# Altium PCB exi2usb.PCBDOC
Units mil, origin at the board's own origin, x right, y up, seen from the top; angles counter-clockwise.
Board outline 1185 x 2070 mil, 4 copper layers (Top Layer, Internal Plane 1, Internal Plane 2, Bottom Layer); 25 components, 72 nets, 205 pads, 65 vias.
Unrouted connection lines stored in the file: 5.
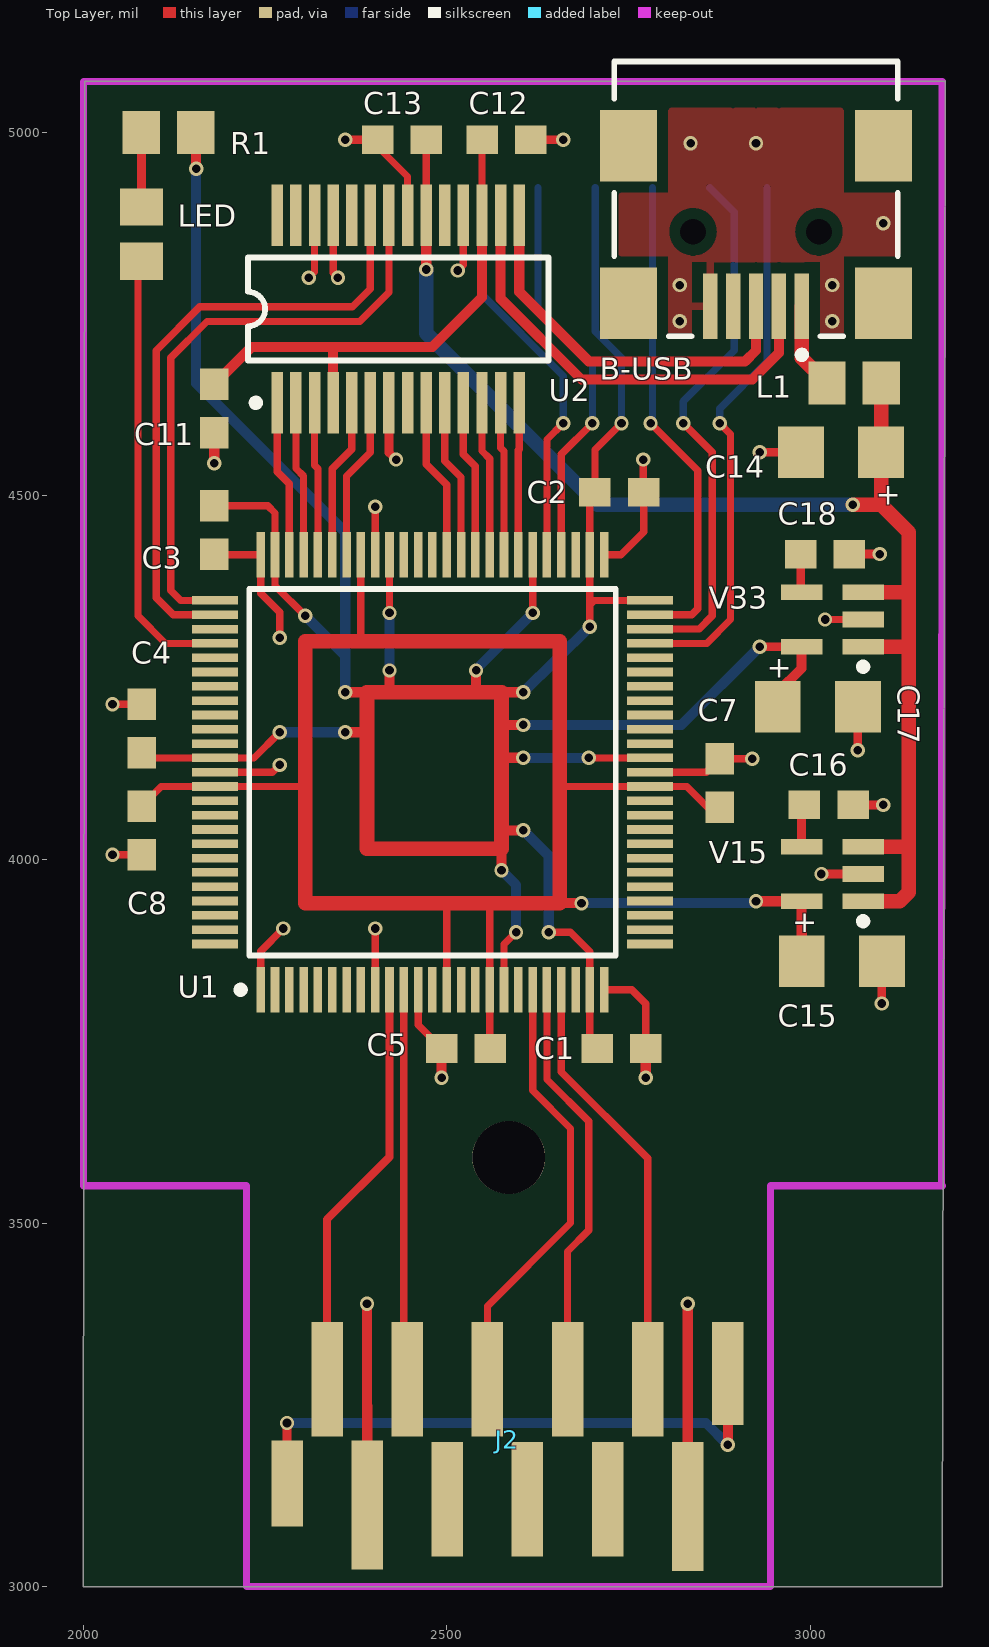
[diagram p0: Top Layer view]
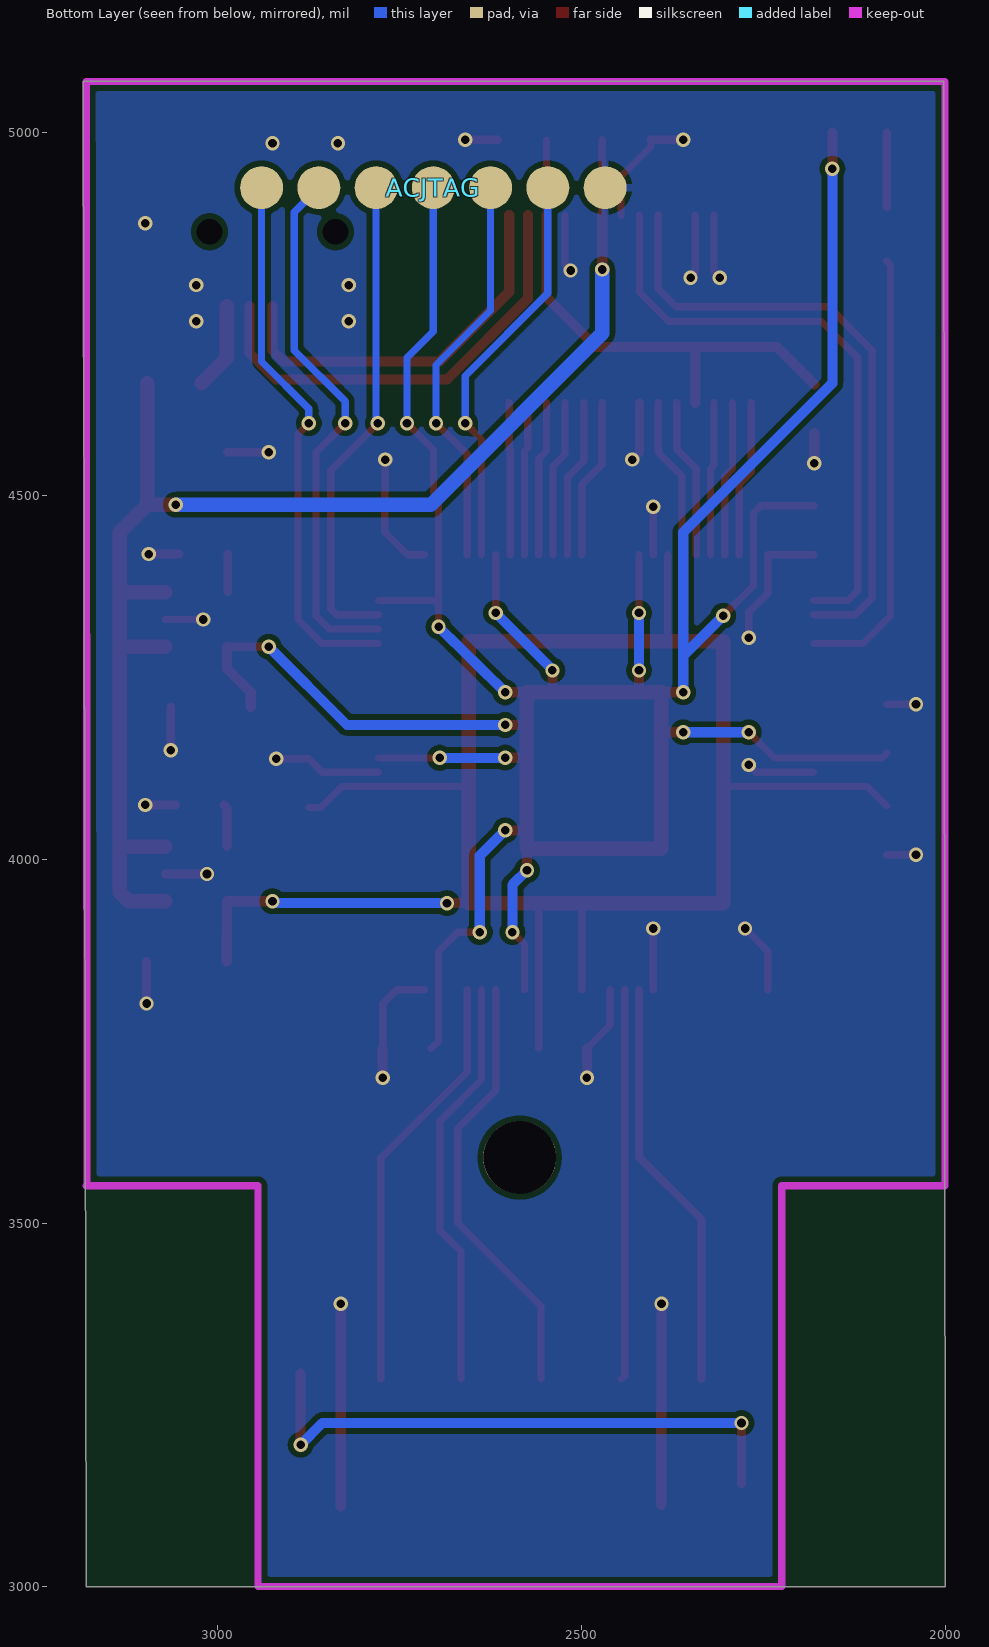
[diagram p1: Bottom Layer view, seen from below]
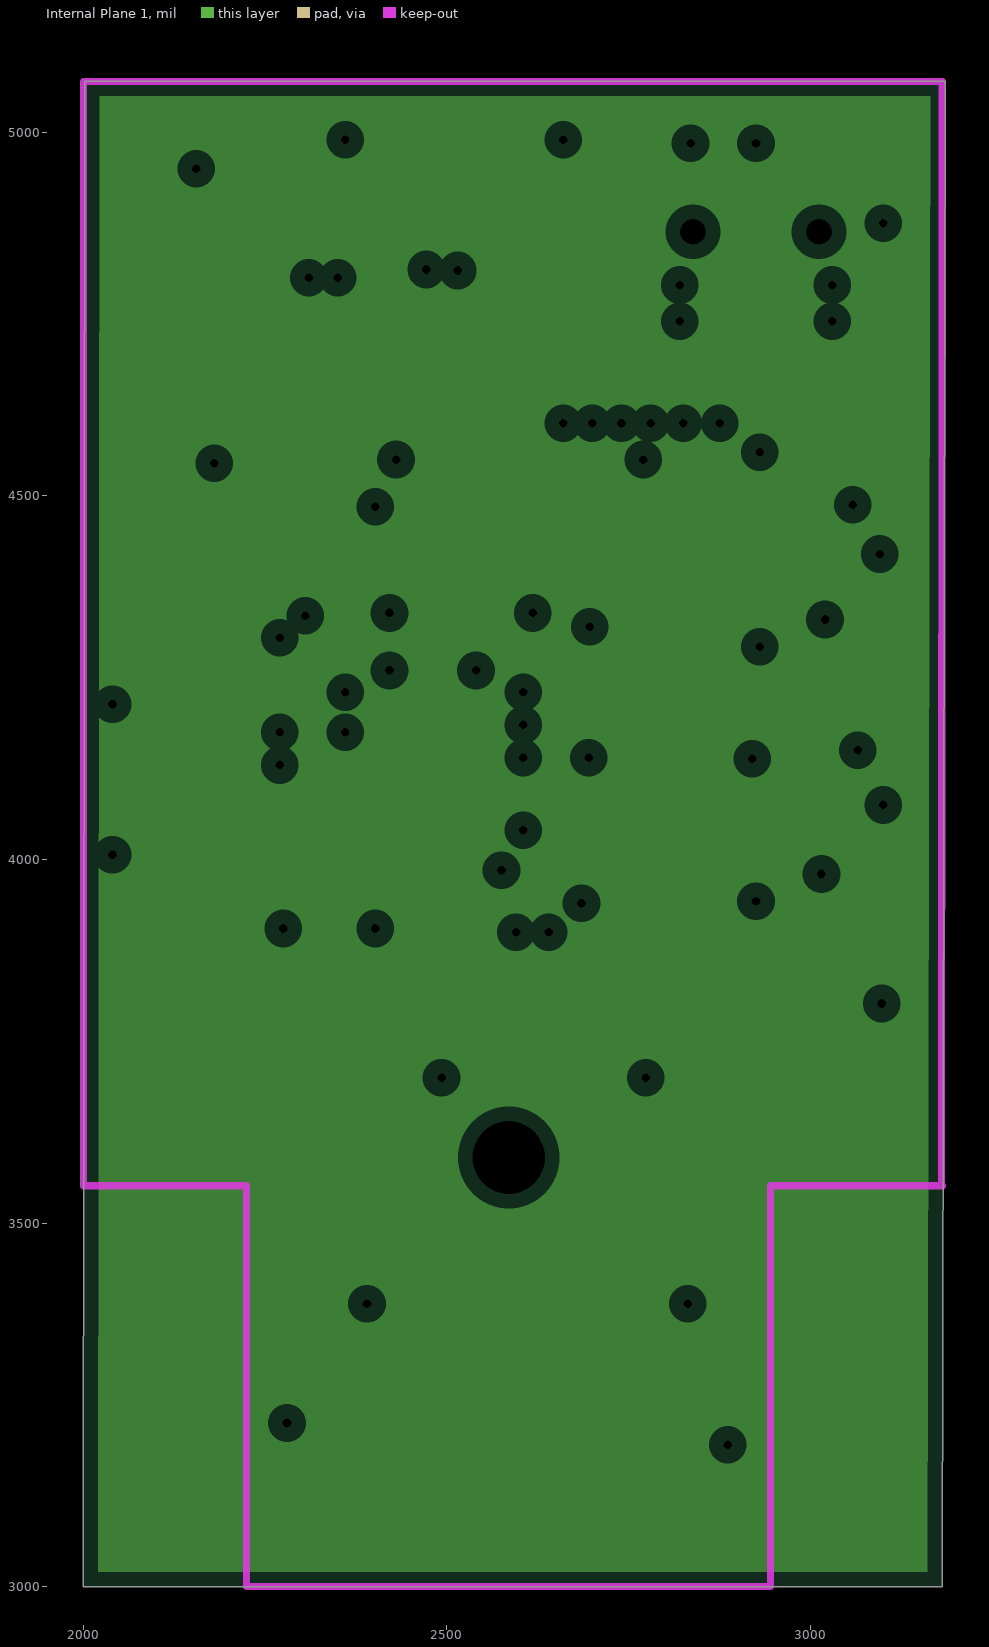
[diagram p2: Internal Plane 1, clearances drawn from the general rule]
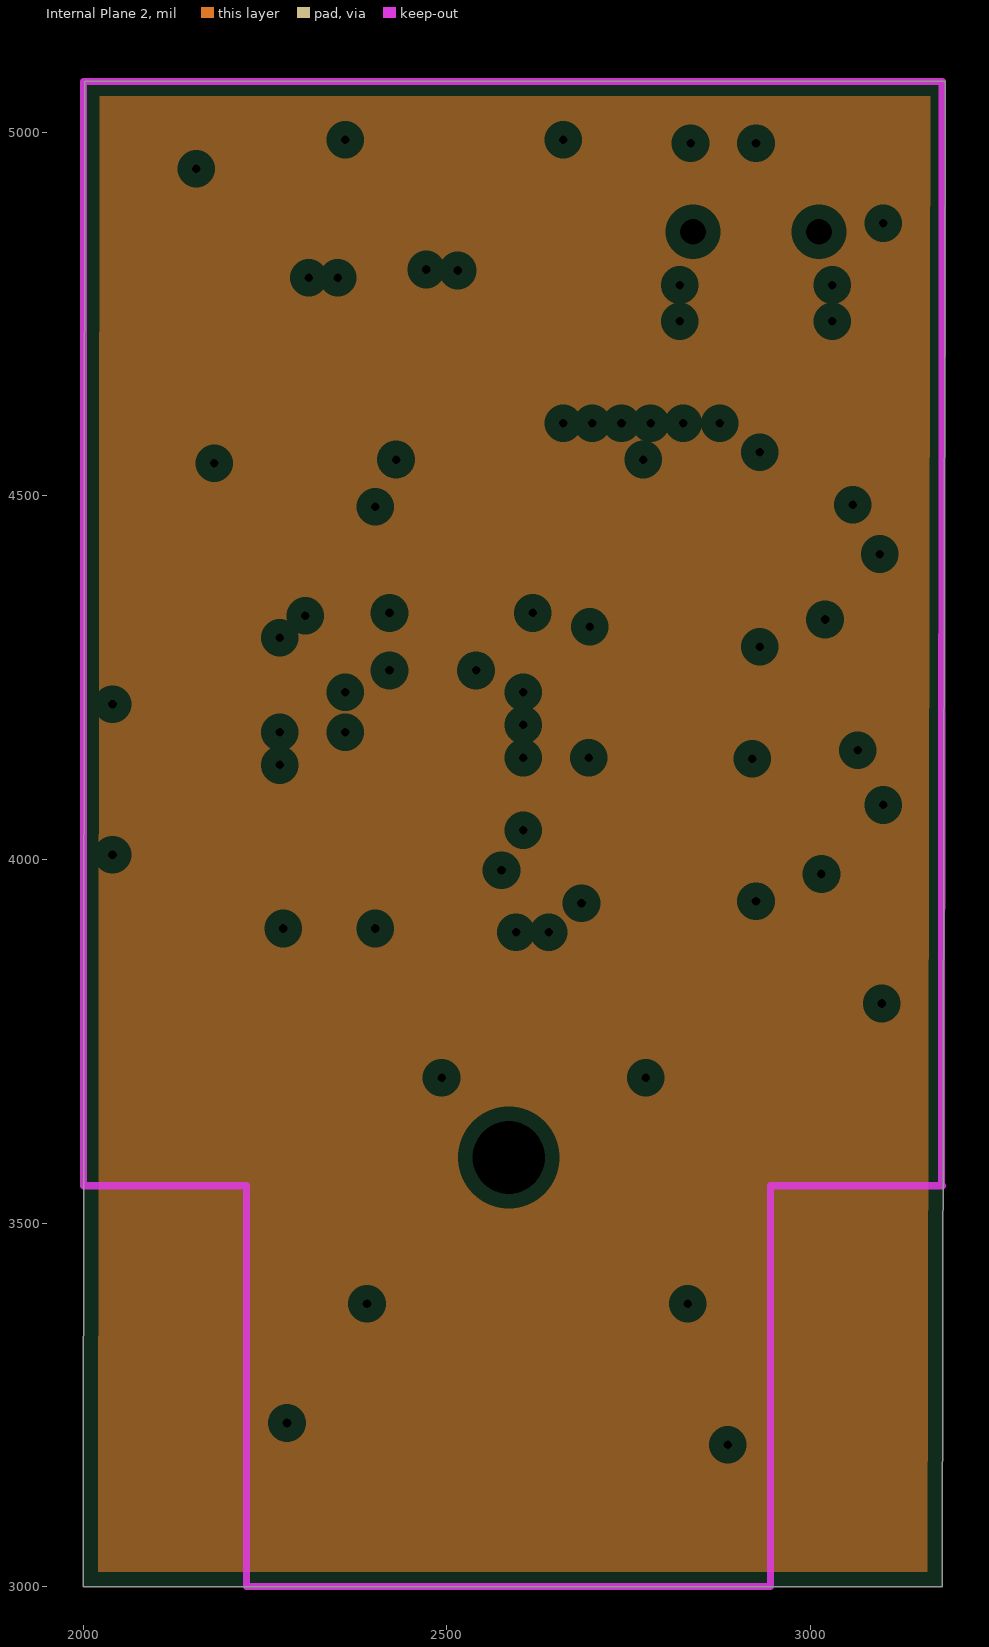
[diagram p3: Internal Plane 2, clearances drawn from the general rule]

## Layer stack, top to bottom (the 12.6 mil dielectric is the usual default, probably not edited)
Top Layer: signal copper 1.4
Dielectric: dielectric 12.6, FR-4, Dk 4.8
Internal Plane 1: plane copper 1.4
Dielectric: dielectric 12.6, FR-4, Dk 4.8
Internal Plane 2: plane copper 1.4
Dielectric: dielectric 12.6, FR-4, Dk 4.8
Bottom Layer: signal copper 1.4

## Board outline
2000,3000 3181.1,3000 3185,5070 2002,5070

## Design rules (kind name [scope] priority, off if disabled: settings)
Clearance [All] p1: gap=7
ComponentClearance [All] p1: gap=10 collisioncheckmode=0
PlaneClearance [All] p1: clearance=20
PlaneConnect [All] p1: planeconnectstyle=Relief reliefexpansion=20 reliefentries=4 reliefconductorwidth=10 reliefairgap=10
PolygonConnect [All] p1: connectstyle=Relief reliefconductorwidth=10 reliefentries=4 polygonreliefangle="90 Angle"
RoomDefinition exi2usb [InComponentClass('exi2usb')] p1: confinementstyle=ConfineIn formatcopy=TRUE outline 0,0 2000,0 2000,1000 0,1000
RoutingLayers [All] p1: top layer=Horizontal bottom layer=Vertical
RoutingVias [All] p1: holewidth=23.62 width=39.37 viastyle="Through Hole" minholewidth=28 minwidth=50 maxholewidth=28 maxwidth=50
SolderMaskExpansion [All] p1: expansion=4
TestPointUsage [All] p1: valid=0 allowmultiple=FALSE
Testpoint [All] p1: side=15 testpointundercomponent=TRUE minsize=40 maxsize=100 preferedsize=60 minholesize=0 maxholesize=40 preferedholesize=32 testpointgrid=1 style=1023 order=1234567890
Width [All] p1: maxlimit=20 minlimit=6 preferedwidth=6
14 further rules are at their usual default settings.

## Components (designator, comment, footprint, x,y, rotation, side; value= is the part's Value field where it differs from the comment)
ACJTAG "JTAG_1" ACTJTAG 2940,4924 r180 bottom
B-USB "USB-Btype" Mini-USB-SMT 2925,5070 r90 top (schematic designator J1)
C1 "CAP603" CAP0603 2740,3740 r0 top
C2 "CAP603" CAP0603 2737,4505 r0 top
C3 "CAP603" CAP0603 2180,4453 r270 top
C4 "CAP603" CAP0603 2080,4180 r90 top
C5 "CAP603" CAP0603 2526,3740 r180 top
C7 "CAP603" CAP0603 2875,4105 r90 top
C8 "CAP603" CAP0603 2080,4040 r270 top
C11 "CAP603" CAP0603 2180,4620 r270 top
C12 "0.1uF" CAP0603 2582,4990 r0 top
C13 "CAP603" CAP0603 2438,4990 r180 top
C14 "TANT1206" CAP1206 3042,4560 r180 top
C15 "TANT1206" CAP1206 3043,3860 r0 top
C16 "CAP603" CAP0603 3025,4075 r0 top
C17 "TANT1206" CAP1206 3010,4210 r0 top
C18 "CAP603" CAP0603 3020,4420 r0 top
J2 "GCMEMPADS" GCMEMPADS 2280,3120 r0 top (schematic designator U4)
L1 "Ferrite Bead" RES0805 3060,4655 r180 top (schematic designator FB1)
LED "LED" RES0805 2080,4860 r90 top (schematic designator R1)
R1 "R1K" RES0805 2117,5000 r180 top (schematic designator R2)
U1 "A3P125" ACTELVQ100 2480,4120 r90 top
U2 "FTDI245RL" SSO-G28/X.4 2433,4757 r0 top
V15 "1.5V Reg" SO-G5/P.95 3030,3980 r90 top
V33 "3.3V Reg" SO-G5/P.95 3030,4330 r90 top

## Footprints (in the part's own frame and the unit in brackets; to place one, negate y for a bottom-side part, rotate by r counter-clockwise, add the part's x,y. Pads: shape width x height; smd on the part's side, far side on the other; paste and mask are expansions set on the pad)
ACTELVQ100 [mm]
  rect 1.6x0.3 smd: 1(-7.6,6) 2(-7.6,5.5) 3(-7.6,5) 4(-7.6,4.5) 5(-7.6,4) 6(-7.6,3.5) 7(-7.6,3) 8(-7.6,2.5) 9(-7.6,2) 10(-7.6,1.5) 11(-7.6,1) 12(-7.6,0.5) 13(-7.6,0) 14(-7.6,-0.5) 15(-7.6,-1) 16(-7.6,-1.5) 17(-7.6,-2) 18(-7.6,-2.5) 19(-7.6,-3) 20(-7.6,-3.5) 21(-7.6,-4) 22(-7.6,-4.5) 23(-7.6,-5) 24(-7.6,-5.5) 25(-7.6,-6) 51(7.6,-6) 52(7.6,-5.5) 53(7.6,-5) 54(7.6,-4.5) 55(7.6,-4) 56(7.6,-3.5) 57(7.6,-3) 58(7.6,-2.5) 59(7.6,-2) 60(7.6,-1.5) 61(7.6,-1) 62(7.6,-0.5) 63(7.6,0) 64(7.6,0.5) 65(7.6,1) 66(7.6,1.5) 67(7.6,2) 68(7.6,2.5) 69(7.6,3) 70(7.6,3.5) 71(7.6,4) 72(7.6,4.5) 73(7.6,5) 74(7.6,5.5) 75(7.6,6)
  rect 0.3x1.6 smd: 26(-6,-7.6) 27(-5.5,-7.6) 28(-5,-7.6) 29(-4.5,-7.6) 30(-4,-7.6) 31(-3.5,-7.6) 32(-3,-7.6) 33(-2.5,-7.6) 34(-2,-7.6) 35(-1.5,-7.6) 36(-1,-7.6) 37(-0.5,-7.6) 38(0,-7.6) 39(0.5,-7.6) 40(1,-7.6) 41(1.5,-7.6) 42(2,-7.6) 43(2.5,-7.6) 44(3,-7.6) 45(3.5,-7.6) 46(4,-7.6) 47(4.5,-7.6) 48(5,-7.6) 49(5.5,-7.6) 50(6,-7.6) 76(6,7.6) 77(5.5,7.6) 78(5,7.6) 79(4.5,7.6) 80(4,7.6) 81(3.5,7.6) 82(3,7.6) 83(2.5,7.6) 84(2,7.6) 85(1.5,7.6) 86(1,7.6) 87(0.5,7.6) 88(0,7.6) 89(-0.5,7.6) 90(-1,7.6) 91(-1.5,7.6) 92(-2,7.6) 93(-2.5,7.6) 94(-3,7.6) 95(-3.5,7.6) 96(-4,7.6) 97(-4.5,7.6) 98(-5,7.6) 99(-5.5,7.6) 100(-6,7.6)
  silkscreen extent -7.72,-6.4 6.4,6.82
ACTJTAG [mm]
  round 1.5 smd: 1(0,0) 2(2,0) 3(4,0) 4(6,0) 5(8,0) 6(10,0) 7(12,0)
CAP0603 [mm]
  rect 1.1x1 smd: 1(-0.85,0) 2(0.85,0)
CAP1206 [mm]
  rect 1.6x1.8 smd: 1(-1.4,0) 2(1.4,0)
GCMEMPADS [mm]
  rect 1.1x3.6 smd: 1(15.4,4.4)
  rect 1.1x4.5 smd: 2(14,-0.25) 10(2.8,-0.2)
  rect 1.1x4 smd: 3(12.6,4.2) 4(11.2,0) 5(9.8,4.2) 6(8.4,0) 7(7,4.2) 8(5.6,0) 9(4.2,4.2) 11(1.4,4.2)
  rect 1.1x3 smd: 12(0,0.55)
Mini-USB-SMT [mm]
  rect 2.3x0.5 smd: 1(-7.85,-1.6) 2(-7.85,-0.8) 3(-7.85,0) 4(-7.85,0.8) 5(-7.85,1.6)
  rect 2.5x2 smd: 6(-7.75,4.45) 7(-2.25,4.45) 8(-7.75,-4.45) 9(-2.25,-4.45)
  round 0.6 hole 0.9 unplated: MH1(-5.25,2.2) MH2(-5.25,-2.2)
  silkscreen extent -9.67,-4.95 0.7,4.95
RES0805 [mm]
  rect 1.3x1.5 smd: 1(-0.95,0) 2(0.95,0)
SO-G5/P.95 [mm]
  rect 0.55x1.45 smd: 1(-0.95,-1.075) 2(0,-1.075) 3(0.95,-1.075) 4(0.95,1.075) 5(-0.95,1.075)
  silkscreen extent -1.77,-1.2 -1.52,-0.95
SSO-G28/X.4 [mm]
  rect 0.4x2.15 smd: 1(-4.225,-3.275) 2(-3.575,-3.275) 3(-2.925,-3.275) 4(-2.275,-3.275) 5(-1.625,-3.275) 6(-0.975,-3.275) 7(-0.325,-3.275) 8(0.325,-3.275) 9(0.975,-3.275) 10(1.625,-3.275) 11(2.275,-3.275) 12(2.925,-3.275) 13(3.575,-3.275) 14(4.225,-3.275) 15(4.225,3.275) 16(3.575,3.275) 17(2.925,3.275) 18(2.275,3.275) 19(1.625,3.275) 20(0.975,3.275) 21(0.325,3.275) 22(-0.325,3.275) 23(-0.975,3.275) 24(-1.625,3.275) 25(-2.275,3.275) 26(-2.925,3.275) 27(-3.575,3.275) 28(-4.225,3.275)
  silkscreen extent -5.25,-3.4 5.25,1.8

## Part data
ACJTAG: "Actel Jtag"
B-USB: "USB B Type Right Angle, SMT 5 Pin"
C1 C2 C3 C4 C5 C7 C8 C11 C13 C16 C18: "Capacitor 603"
C12: library part CAP603, "Capacitor 603"
C14 C15 C17: "Tant 1206 A106 J106"
J2: "Gamecube Memory Card Pads"
L1 LED R1: library part RESISTOR805, "Resistor 805 Package"
U1: "Actel Proasic3 A3P125 100 Pin"
U2: "FTDI 245RL 28 pin SSOP"
V15 V33: library part SOT23-5, "AIC1733-XXPV"

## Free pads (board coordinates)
  round 100 hole 100 unplated: 0(2585,3590)

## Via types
v1: diameter 19.68, hole 11.81, Top Layer to Bottom Layer, 65 vias

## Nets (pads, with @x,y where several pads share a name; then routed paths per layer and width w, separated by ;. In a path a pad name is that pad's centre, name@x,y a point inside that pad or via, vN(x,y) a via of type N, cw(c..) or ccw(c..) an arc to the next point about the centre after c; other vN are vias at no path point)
33VCCIO: 
A0: 
A1: 
A2: 
A3: 
A4: 
A5: 
A6: 
A7: 
A8: 
A9: 
A10: 
A11: 
A12: 
A13: 
A14: 
A15: 
A16: 
A17: 
A18: 
CE#: 
D0: 
D1: 
D2: 
D3: 
D4: 
D5: 
D6: 
D7: 
EXT: J2.1 J2.12 | length 800.3
  Top Layer w12: J2.12 v1(2280,3225)
  Top Layer w14: v1(2886.3,3195) J2.1
  Bottom Layer w14: v1(2280,3225) 2856.3,3225 v1(2886.3,3195)
GCCLK: J2.11 U1.10 | length 571
  Top Layer w11: J2.11 2335.12,3505.12 2420.95,3590.95 U1.10
GCCS: J2.9 U1.11 | length 537.4
  Top Layer w10: U1.11 2440.63,3290.08 J2.9
GCDI: J2.7 U1.20 | length 664.7
  Top Layer w10: J2.7@2555.59,3345.59 J2.7 2555.59,3385.59 2670,3500 2670,3630 2617.8,3682.2 U1.20
GCDO: J2.5 U1.21 | length 571.3
  Top Layer w10: U1.21 2637.48,3697.52 2695,3640 2695,3490 2665.83,3460.83 J2.5
GCINT: J2.3 U1.22 | length 584.7
  Top Layer w10: U1.22 2657.16,3707.84 2776.06,3588.94 J2.3
GND: ACJTAG.7 B-USB.5 C1.2 C2.2 C3.2 C4.2 C5.2 C7.2 C8.2 C11.2 C12.2 C13.2 C14.2 C15.2 C16.2 C17.2 C18.2 J2.2 J2.10 U1.1 U1.9 U1.12 U1.25 U1.38 U1.51 U1.67 U1.75 U1.88 U2.7 U2.18 U2.21 U2.25 U2.26 V15.2 V33.2 | length 2738.4
  Top Layer w10: v1(2040,4006.53) C8.2 ; v1(2040,4213.47) C4.2 ; C3.2@2180.32,4419.21 U1.75 2243.78,4366.22 2270,4340 v1(2270,4305) ; U1.88 2260,4120 v1(2270,4130) ; U1.1 2243.78,3873.78 v1(2275,3905) ; v1(2310,4800) 2317.84,4807.84 U2.26 ; U2.25 2343.43,4806.57 v1(2350,4800) ; U1.9 v1(2401.26,3905) ; U1.67 v1(2401.26,4485) ; C13.2 2404.53,4980.47 2445.8,4939.2 U2.21 ; U1.12 2460.32,3772.22 C5.2 ; v1(2515,4810) 2522.57,4817.57 U2.18 ; U1.25 2754.21,3820.79 2773.47,3801.53 C1.2 ; U1.51 2739.21,4419.21 2770.47,4450.47 C2.2 ; C2.2@2770,4505.47 v1(2770,4550) ; U1.38 2856.53,4120 C7.2 v1(2920,4138.47) ; v1(3020,4330) V33.2
  Top Layer w12: v1(2360,4990) C13.2 ; U2.7 2420.2,4559.8 v1(2430,4550) ; C12.2 v1(2660,4990) ; v1(2930,4560) C14.2 ; v1(3015,3980) V15.2 ; C18.2 v1(3095,4420) ; C16.2 v1(3100,4075) ; v1(3065,4150) C17.2@3065,4209.88 ; v1(3098.12,3801.88) C15.2
  Top Layer w14: v1(2180,4545) C11.2 ; v1(2390,3388.82) J2.10 ; v1(2492.53,3700) C5.2 ; v1(2773.47,3700) C1.2 ; J2.2 v1(2831.18,3388.82)
  other v1: 2820,4740 3030,4740 2820,4790 3030,4790 3100,4875 2835,4985 2925,4985
LED: LED.1 LED.2 R1.2 U1.79 | length 713.3
  Top Layer w10: LED.1 2075,4817.6 2075,4335 2112.84,4297.16 U1.79
  Top Layer w12: LED.2 R1.2@2080,4999.6
Net_1: 
Net_1: 
Net_6: 
NetC16_1: C16.1 V15.4 | length 59.2
  Top Layer w12: V15.4 2987.68,4071.14 C16.1
NetC18_1: C18.1 V33.4 | length 51.5
  Top Layer w12: V33.4@2986.53,4368.54 C18.1
NetU1_26: U1.26
NetU1_27: U1.27
NetU1_29: U1.29
NetU1_30: U1.30
OE#: 
TCK: ACJTAG.1 U1.47 | length 751.5
  Top Layer w10: U1.47 2857.16,4297.16 2890,4330 2890,4585 v1(2875,4600)
  Bottom Layer w10: v1(2875,4600) 2875,4620 2940,4685 ACJTAG.1
TDI: ACJTAG.2 U1.48 | length 741.8
  Top Layer w10: U1.48@2779.21,4316.85 2846.85,4316.85 2865,4335 2865,4560 v1(2825,4600)
  Bottom Layer w10: v1(2825,4600) 2825,4630 2895,4700 2895,4890.26 ACJTAG.2
TDO: ACJTAG.5 U1.54 | length 553.6
  Top Layer w10: U1.54 2657.16,4557.16 v1(2700,4600)
  Bottom Layer w10: ACJTAG.5 2625.04,4754.96 2700,4680 v1(2700,4600)
TMS: ACJTAG.3 U1.49 | length 676.3
  Top Layer w10: U1.49 2836.53,4336.53 2845,4345 2845,4535 v1(2780,4600)
  Bottom Layer w10: v1(2780,4600) 2782.52,4602.52 ACJTAG.3
TRST: ACJTAG.6 U1.55 | length 561.2
  Top Layer w10: U1.55 2637.48,4577.48 v1(2660,4600)
  Bottom Layer w10: ACJTAG.6 2546.3,4778.7 2660,4665 v1(2660,4600)
USBD0: U1.73 U2.1 | length 215.7
  Top Layer w10: U2.1 2266.66,4533.34 2283.15,4516.85 U1.73
USBD1: U1.70 U2.5 | length 220
  Top Layer w10: U1.70 2342.2,4537.2 2369.02,4564.02 U2.5
USBD2: U1.71 U2.3 | length 210.8
  Top Layer w10: U2.3 2317.84,4542.16 2322.52,4537.48 U1.71
USBD3: U1.60 U2.11 | length 215.7
  Top Layer w10: U2.11 2522.57,4557.43 2539.05,4540.94 U1.60
USBD4: U1.72 U2.2 | length 213.2
  Top Layer w10: U2.2 2292.25,4537.75 2302.83,4527.17 U1.72
USBD5: U1.62 U2.9 | length 220.6
  Top Layer w10: U2.9 2471.39,4543.61 2499.68,4515.31 U1.62
USBD6: U1.61 U2.10 | length 218.1
  Top Layer w10: U2.10 2496.98,4548.02 2519.37,4525.63 U1.61
USBD7: U1.69 U2.6 | length 222.4
  Top Layer w10: U1.69 2361.89,4526.89 2394.61,4559.61 U2.6
USBDM: B-USB.2 U2.16 | length 623.1
  Top Layer w14: U2.16 2573.75,4771.25 2685,4660 2920,4660 2956.5,4696.5 B-USB.2
USBDP: B-USB.3 U2.15 | length 537.7
  Top Layer w14: U2.15 2599.34,4780.66 2695,4685 2910,4685 2925,4700 B-USB.3
USBPWREN: U1.59 U2.12 | length 213.2
  Top Layer w10: U2.12 2548.16,4561.84 2558.74,4551.26 U1.59
USBRD#: U1.58 U2.13 | length 210.8
  Top Layer w10: U2.13 2573.75,4566.25 2578.43,4561.57 U1.58
USBRXF: U1.77 U2.23 | length 861.5
  Top Layer w10: U1.77 2123.47,4336.53 2100,4360 2100,4700 2160,4760 2370,4760 2394.61,4784.61 U2.23
USBRXF#: 
USBTXE#: U1.76 U2.22 | length 829.8
  Top Layer w10: U1.76 2133.78,4356.22 2120,4370 2120,4690 2170,4740 2380,4740 2420.2,4780.2 U2.22
USBWR: U1.57 U2.14 | length 209.4
  Top Layer w10: U1.57 2598.11,4563.11 2599.34,4564.34 U2.14
VCC5: B-USB.1 C13.1 C14.1 L1.1 L1.2 U2.20 V15.1 V15.3 V33.1 V33.3 | length 2073.8
  Top Layer w10: U2.20 C13.1@2471.39,4989.92
  Top Layer w14: v1(2471.39,4811.39) U2.20
  Top Layer w19.68: B-USB.1 2987.99,4689.61 L1.2 ; v1(3057.88,4487.88) 3097.12,4487.88 ; V15.1 3122.6,3942.6 3135,3955 3135,4450 3097.12,4487.88 ; V15.3 3132.6,4017.4 ; V33.1 3132.6,4292.6 ; V33.3 3132.4,4367.4 ; C14.1 3097.12,4487.88 ; C14.1@3097.4,4560.28 L1.1
  Bottom Layer w19.68: v1(2471.39,4811.39) 2471.39,4783.61 2471.39,4723.61 2707.12,4487.88 v1(3057.88,4487.88)
VCC15: C5.1 C7.1 C8.1 C15.1 U1.14 U1.17 U1.37 U1.68 U1.89 V15.5 | length 2738.8
  Top Layer w10: C8.1 2106.85,4100.31 U1.89 2304.68,4100.31 ; 2381.57,4301.57 U1.68 ; U1.14 2499.68,3939.68 2500,3940 ; C5.1@2558.74,3740.72 U1.17 2558.74,3938.74 ; 2655.32,4100.31 U1.37 2829.68,4100.31 2858.47,4071.53 C7.1
  Top Layer w14: 2655,3940 v1(2685,3940) ; v1(2925,3942.6) V15.5 C15.1
  Top Layer w20: 2305,3940 2305,4300 2655,4300 2655,3940 2305,3940
  Bottom Layer w14: v1(2685,3940) 2922.4,3940 v1(2925,3942.6)
VCC33: ACJTAG.4 C1.1 C2.1 C3.1 C4.1 C11.1 C12.1 C17.1 J2.4 J2.8 R1.1 U1.18 U1.24 U1.39 U1.50 U1.52 U1.56 U1.66 U1.74 U1.87 U2.4 U2.17 V33.5 | length 5692.4
  Top Layer w10: C4.1 2086.85,4139.69 U1.87 2234.68,4139.69 v1(2270,4175) ; C3.1 2253.53,4486.47 2263.46,4476.54 U1.74 2263.46,4376.54 v1(2305,4335) ; v1(2420.95,4339.06) U1.66 ; U2.17 C12.1@2548.16,4989.62 ; U1.18 2578.43,3883.43 v1(2595,3900) ; v1(2617.8,4339.06) U1.56 ; v1(2640,3900) 2670,3900 2696.53,3873.47 U1.24 2696.53,3750 C1.1 ; v1(2695,4139.69) U1.39 ; v1(2696.53,4320) U1.52 2696.53,4498 C2.1 2703.53,4563.53 v1(2740,4600) ; 2696.53,4350 2702.76,4356.22 U1.50
  Top Layer w12: v1(2930,4292.6) V33.5
  Top Layer w14: v1(2155,4950) R1.1@2155,4999.4 ; C11.1 2231.53,4705 2343.43,4705 ; U2.4 2343.43,4705 ; v1(2360,4175) 2390,4175 ; v1(2360,4230) 2390,4230 ; 2420.95,4230.94 v1(2420.95,4260) ; 2540,4230 v1(2540,4260) ; U2.17 2548.16,4773.16 2480,4705 2343.43,4705 ; v1(2575,3985) 2575,4015 ; 2575,4040 v1(2605,4040) ; 2575,4140 v1(2605,4140) ; 2575,4185 v1(2605,4185) ; 2575,4230 v1(2605,4230) ; C17.1 2954.88,4229.88 2987.68,4262.68 V33.5
  Top Layer w20: 2390,4015 2390,4230 2575,4230 2575,4015 2390,4015
  Bottom Layer w10: ACJTAG.4 2703.78,4726.22 2740,4690 v1(2740,4600)
  Bottom Layer w14: v1(2155,4950) 2155,4655 2360,4450 2360,4280 ; v1(2270,4175) v1(2360,4175) ; v1(2305,4335) 2360,4280 ; v1(2360,4230) 2360,4280 ; v1(2420.95,4260) v1(2420.95,4339.06) ; v1@2540,4261.26 v1(2617.8,4339.06) ; v1(2575,3985) 2595,3965 v1(2595,3900) ; v1(2605,4040) 2640,4005 v1(2640,3900) ; v1(2605,4185) 2822.4,4185 v1(2930,4292.6) ; v1(2605,4230) v1(2696.53,4320) ; v1@2605.32,4139.69 v1(2695,4139.69)
WE#: 
pads on no net: B-USB.4 B-USB.6 B-USB.7 B-USB.8 B-USB.9 B-USB.MH1 B-USB.MH2 J2.6 U1.2 U1.3 U1.4 U1.5 U1.6 U1.7 U1.8 U1.13 U1.15 U1.16 U1.19 U1.23 U1.28 U1.31 U1.32 U1.33 U1.34 U1.35 U1.36 U1.40 U1.41 U1.42 U1.43 U1.44 U1.45 U1.46 U1.53 U1.63 U1.64 U1.65 U1.78 U1.80 U1.81 U1.82 U1.83 U1.84 U1.85 U1.86 U1.90 U1.91 U1.92 U1.93 U1.94 U1.95 U1.96 U1.97 U1.98 U1.99 U1.100 U2.8 U2.19 U2.24 U2.27 U2.28

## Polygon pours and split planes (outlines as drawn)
GND on Top Layer (hatched 90Degree grid 1 track 8, remove dead copper): 2740,5030 3120,5030 3120,4725 2740,4725
GND on Bottom Layer (hatched 90Degree grid 1 track 8, remove dead copper): 2010,5060 3165,5060 3165,3010 2005,3010
no net on Internal Plane 1 (split plane): 2020.03,3020.01 2022,5049.98 3164.95,5049.98 3161.12,3020.01
no net on Internal Plane 2 (split plane): 2020.03,3020.01 2022,5049.98 3164.95,5049.98 3161.12,3020.01

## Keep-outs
Keep-Out Layer:
  lines w10: 3180,3551.18 3181.1,5070 2000,5070 2000,3551.18 2224.41,3551.18 2224.41,3000 2944.88,3000 2944.88,3551.18 3181.1,3551.18

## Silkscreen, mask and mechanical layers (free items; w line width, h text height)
Top Overlay:
  text "+" at 3090,4487.88 h30
  text "+" at 2940,4250 h30
  text "+" at 2975,3900 h30
Drill Drawing:
  text "Drill Drawing." at 3560,3355 h60
  text ".LEGEND" at 3490,3230 h60

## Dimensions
2000,3551.18 to 2000,5070 on Mechanical 1
2224.41,3000 to 2944.88,3000 on Mechanical 1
